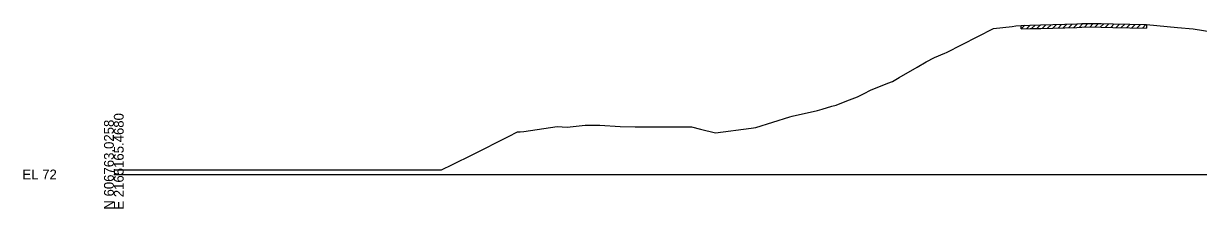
# Model space of a CAD drawing. Extents: x -26 to 6803, y -10 to 19606.
# Drawn here: x 3974.3 to 4308.5, y 17990.3 to 18043 of the extents above; entities that cross this region are included whole.
import ezdxf

# ---------------------------------------------------------------- set-up
doc = ezdxf.new("R2010")
doc.units = 0
for name, color, linetype in [('RD_GPK_XS_Cell', 7, 'Continuous'), ('RD_XS_ExGround', 7, 'Continuous'), ('RD_XS_ExPaveRet', 7, 'Continuous')]:
    doc.layers.add(name, color=color, linetype=linetype)

msp = doc.modelspace()

# ---------------------------------------------------------------- linework, layer by layer
at = {"layer": 'RD_GPK_XS_Cell'}
msp.add_line((4000, 18000), (4400, 18000), dxfattribs=at)
at = {"layer": 'RD_XS_ExGround'}
msp.add_lwpolyline([(4000, 18001.34), (4008.99, 18001.34), (4093.17, 18001.34), (4096.31, 18002.89), (4102.13, 18005.71), (4112.26, 18010.78), (4114.8, 18012.17), (4115.58, 18012.16), (4116.56, 18012.25), (4126.05, 18013.66), (4128.9, 18013.5), (4134.06, 18014.06), (4134.8, 18014.08), (4138.24, 18014.07), (4143.97, 18013.63), (4148.26, 18013.58), (4150.73, 18013.6), (4162.65, 18013.56), (4164.31, 18013.56), (4166.85, 18012.88), (4171.12, 18011.82), (4181.24, 18013.16), (4182.59, 18013.37), (4192.25, 18016.44), (4192.88, 18016.59), (4200.08, 18018.21), (4201.44, 18018.64), (4204.21, 18019.43), (4205.41, 18019.76), (4208.41, 18020.96), (4211.48, 18022.14), (4213.37, 18023.03), (4215.16, 18023.97), (4220.13, 18025.97), (4221.41, 18026.5), (4223.31, 18027.67), (4228.44, 18030.58), (4230.98, 18032.05), (4233.41, 18033.28), (4236.35, 18034.54), (4236.8, 18034.76), (4250.18, 18041.62), (4255.45, 18042.19), (4256.55, 18042.33), (4258.02, 18042.46), (4260.59, 18042.55), (4263.67, 18042.59), (4273.82, 18042.86), (4275.25, 18042.97), (4277.91, 18043.01), (4280.75, 18042.96), (4284.1, 18042.88), (4293.7, 18042.69), (4302.46, 18041.84), (4306.97, 18041.5), (4312.22, 18040.67)], dxfattribs=at)
at = {"layer": 'RD_XS_ExPaveRet'}
for p, q in [((4258.02, 18041.46), (4259.05, 18042.5)), ((4258.02, 18041.46), (4258.02, 18042.46)), ((4258.02, 18041.46), (4260.59, 18041.55)), ((4258.02, 18041.46), (4258.02, 18041.46)), ((4259.52, 18041.51), (4260.55, 18042.55)), ((4260.59, 18041.55), (4263.67, 18041.59)), ((4261.02, 18041.55), (4262.03, 18042.57)), ((4262.52, 18041.57), (4263.53, 18042.59)), ((4263.67, 18041.59), (4273.82, 18041.86)), ((4264.02, 18041.6), (4265.05, 18042.63)), ((4265.52, 18041.64), (4266.55, 18042.67)), ((4267.02, 18041.68), (4268.05, 18042.71)), ((4268.52, 18041.72), (4269.55, 18042.75)), ((4270.02, 18041.76), (4271.05, 18042.79)), ((4271.52, 18041.8), (4272.55, 18042.83)), ((4273.02, 18041.84), (4274.06, 18042.88)), ((4273.82, 18041.86), (4275.25, 18041.97)), ((4274.52, 18041.91), (4275.58, 18042.97)), ((4275.25, 18041.97), (4277.91, 18042.01)), ((4276.02, 18041.98), (4277.04, 18043)), ((4277.52, 18042), (4278.52, 18043)), ((4277.91, 18042.01), (4280.75, 18041.96)), ((4279.02, 18041.99), (4280, 18042.97)), ((4280.52, 18041.96), (4281.5, 18042.94)), ((4280.75, 18041.96), (4284.1, 18041.88)), ((4282.02, 18041.93), (4283, 18042.9)), ((4283.52, 18041.89), (4284.5, 18042.87)), ((4284.1, 18041.88), (4293.7, 18041.69)), ((4285.02, 18041.86), (4286, 18042.84)), ((4286.52, 18041.83), (4287.5, 18042.81)), ((4288.02, 18041.8), (4289, 18042.78)), ((4289.52, 18041.77), (4290.5, 18042.75)), ((4291.02, 18041.74), (4292, 18042.72)), ((4292.52, 18041.71), (4293.5, 18042.69)), ((4293.7, 18042.69), (4293.7, 18041.69))]:
    msp.add_line(p, q, dxfattribs=at)

# ---------------------------------------------------------------- texts
at = {"layer": 'RD_GPK_XS_Cell'}
for s, p in [('N 606763.0258', (4000, 17990)), ('E 2165165.4680', (4002.8, 17990))]:
    msp.add_text(s, height=2.8, rotation=90, dxfattribs=at).set_placement(p)
msp.add_text('EL 72', height=2.8, dxfattribs=at).set_placement((3974, 17998.6))

doc.saveas('drawing.dxf')
